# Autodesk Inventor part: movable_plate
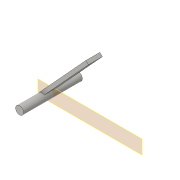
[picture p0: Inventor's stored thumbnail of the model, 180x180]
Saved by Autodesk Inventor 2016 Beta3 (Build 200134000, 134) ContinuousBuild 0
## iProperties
Created: 2016-03
Part Number: movable_plate
Material: Generic
Document SubType Name: Modeling
Designer: Gaurav
Density: 1 g/cm^3
Appearance: Default
Author: Gaurav
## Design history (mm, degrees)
workplane "Work Plane1"
sketch "Sketch2"
  geometry: L1 (-22.105, 11.375)-(36.065, 74.959); L2 (36.065, 74.959)-(39.28, 72.017); L3 (39.28, 72.017)-(-15.542, 12.092); A1 r 5 centre (-18.416, 8) between (-22.105, 11.375) and (-15.542, 12.092) reference; A2 r 5 centre (-18.416, 8) between (-13.416, 8) and (-18.416, 3) reference; A3 r 5 centre (-18.416, 8) between (-15.542, 12.092) and (-21.951, 11.536); 1 further point
  constraints: 6 end point, 5 point on circle, 1 centre point, 1 parallel, 1 perpendicular, 1 tangent
extrude "Extrusion2" join sketch "Sketch2" stored distance "d2" = 17.4625; taper "d3" = 0 deg
sketch "Sketch3"
  geometry: C1 r 5 at (-18.416, 8); A1 r 5 centre (-18.416, 8) between (-15.542, 12.092) and (-22.105, 11.375) reference; 1 further point
  constraints: 1 centre point, 1 coincident, 1 concentric
extrude "Extrusion3" join sketch "Sketch3" stored distance "d4" = 73.025; taper "d5" = 0 deg
body "Solid1"
node "Reference3"
